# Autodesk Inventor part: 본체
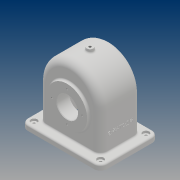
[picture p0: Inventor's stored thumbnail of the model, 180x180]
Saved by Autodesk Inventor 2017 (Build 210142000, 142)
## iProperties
Part Number: 본체
Material: 일반
Document SubType Name: Modeling
Designer: 20
Density: 1 g/cm^3
Appearance: 기본값
Author: 20
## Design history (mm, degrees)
sketch "스케치1"
  geometry: L1 (58, 13)-(58, -65); L2 (58, -65)-(-58, -65); L3 (-58, -65)-(-58, 13); A1 r 58 centre (0, 13) between (58, 13) and (-58, 13); 1 further point
  constraints: 6 end point, 2 point on circle, 2 tangent, 2 vertical, 1 centre point, 1 horizontal
  dimensions: "d0" = 58 distance from line of point (0, 0) L3; "d1" = 116 distance of L1.end L2.end; "d2" = 78 distance from line of A1.centre L2; "d3" = 65 distance from line of L2 point (0, 0); "d4" = 58 radius of A1 (derived)
extrude "돌출1" new body sketch "스케치1" stored distance "d5" = 77; taper "d6" = 0 deg
sketch "스케치2"
  geometry: L1 (58, -65)-(58, 13) reference; L2 (-58, 13)-(-58, -65) reference; L3 (52, -65)-(52, 13); L4 (-52, 13)-(-52, -65); L5 (52, -65)-(-52, -65); L6 (-58, -65)-(58, -65) reference; A1 r 58 centre (0, 13) between (58, 13) and (-58, 13) reference; A2 r 52 centre (0, 13) between (52, 13) and (-52, 13); 1 further point
  constraints: 6 end point, 2 point on circle, 1 centre point, 1 collinear, 1 horizontal, 2 other
  dimensions: "d9" = 6 distance between parallel lines of L1 L3
extrude "돌출2" cut sketch "스케치2" stored distance "d10" = 67; taper "d11" = 0 deg
sketch "스케치3"
  geometry: L1 (-64.83, 0)-(80.389, 0); L2 (33.5, -65)-(-33.5, -65) reference; L3 (33.5, 38)-(48.5, 38); L4 (48.5, 38)-(48.5, 20); L5 (48.5, 20)-(33.5, 20); L6 (33.5, 20)-(33.5, 38); L7 (33.5, 13)-(33.5, 65) reference; L8 (-38.5, 71)-(-38.5, 13) reference; L9 (-33.5, 65)-(-33.5, 13) reference; L10 (-33.5, 39.747)-(-19.5, 28); L11 (-19.5, 28)-(-19.5, 20); L12 (-19.5, 20)-(-43.5, 20); L13 (-43.5, 20)-(-43.5, 38); L14 (-43.5, 38)-(-38.5, 38); L15 (-38.5, 38)-(-38.5, 39.747); L16 (-38.5, 39.747)-(-33.5, 39.747); 1 further point
  constraints: 24 end point, 5 horizontal, 2 collinear, 2 parallel, 2 vertical, 1 perpendicular, 1 point on line
  dimensions: "d12" = 65 distance between parallel lines of L1 L2; "d14" = 40 diameter of L5 L1; "d15" = 76 diameter of L3 L1; "d16" = 87 distance between parallel lines of L4 L8; "d22" = 5 distance between parallel lines of L9 L8 (derived); "d23" = 15 distance of L4.end L5.end (derived); "d24" = 40 diameter of L12 L1; "d25" = 56 diameter of L10.end L1; "d26" = 76 diameter of L14 L1; "d27" = 24 distance of L11.end L12.end; "d29" = 5 distance between parallel lines of L8 L13; "d30" = 50 deg angle of L11 L10
revolve "회전1" sketch "스케치3" stored, may be unused: angle "d31" = 90 deg
sketch "스케치4"
  geometry: C1 r 20 at (0, 0) reference; C2 r 20 at (0, 0); 1 further point
  constraints: 1 centre point, 1 coincident
  dimensions: "d32" = 40 diameter of C2
extrude "돌출3" cut sketch "스케치4" stored distance "d33" = 67; taper "d34" = 0 deg
sketch "스케치5"
  geometry: L1 (-17, 16.5)-(133, 16.5); L2 (133, 16.5)-(133, -93.5); L3 (133, -93.5)-(-17, -93.5); L4 (-17, -93.5)-(-17, 16.5); L5 (-17, 16.5)-(133, -93.5); L6 (133, 16.5)-(-17, -93.5); L7 (6, -72)-(110, -72) reference; L8 (110, -5)-(6, -5); L9 (6, -5)-(6, -72); L10 (6, -72)-(110, -72); L11 (110, -72)-(110, -5); L12 (110, -5)-(6, -72); L13 (6, -5)-(110, -72); 2 further points
  constraints: 24 end point, 6 midpoint, 4 parallel, 2 horizontal, 2 perpendicular
  dimensions: "d35" = 150 distance of L2.end L3.end; "d36" = 110 distance of L1.end L2.end
extrude "돌출4" join sketch "스케치5" distance "d37" = 10; taper "d38" = 0 deg
node "작업 평면1"
sketch "스케치6"
  geometry: C1 r 6 at (75, -55); 1 further point
  constraints: 1 centre point, 1 coincident
  dimensions: "d40" = 12 diameter of C1
extrude "돌출5" join sketch "스케치6" stored distance "d41" = 10; taper "d42" = 0 deg
hole "구멍1" diameter "d45" = 4.459; stored, may be unused: countersink angle "d49" = 90 deg, drill point angle "d51" = 118 deg; dims "d43" = 10, "d44" = 10, "d46" = 10, "d47" = 4, "d48" = 2, "d50" = 50
fillet "모깎기1" dims "d52" = 12
sketch "스케치8"
  geometry: A1 r 12 centre (-121, 4.5) between (-121, 16.5) and (-133, 4.5) reference; 2 further points
  constraints: 1 coincident
hole "구멍2" sketch "스케치8" at (-121, 4.5) diameter "d53" = 5; stored, may be unused: countersink angle "d57" = 90 deg, drill point angle "d59" = 118 deg; dims "d54" = 10, "d55" = 12, "d56" = 4, "d58" = 50
fillet "모깎기2" dims "d66" = 13
fillet "모깎기3" dims "d67" = 8
fillet "모깎기5" dims "d69" = 3
chamfer "모따기1" distance "d70" = 1; stored, may be unused: second distance "d71" = 2, angle "d72" = 45 deg
sketch "스케치9"
  geometry: 2 further points
  constraints: 1 vertical alignment
  dimensions: "d73" = 29 distance of point (0, 0) point (0, 29)
hole "구멍3" sketch "스케치9" at (0, 29) diameter "d74" = 3.242; stored, may be unused: countersink angle "d78" = 90 deg, drill point angle "d80" = 118 deg; dims "d75" = 8, "d76" = 12, "d77" = 4, "d79" = 10
sketch "스케치10"
  geometry: C1 r 1.621 at (0, -29) reference; 2 further points
  constraints: 1 coincident
hole "구멍4" sketch "스케치10" at (0, -29) diameter "d84" = 3.242; stored, may be unused: countersink angle "d88" = 90 deg, drill point angle "d90" = 118 deg; dims "d85" = 8, "d86" = 12, "d87" = 4, "d89" = 10
fillet "모깎기6" dims "d94" = 3
sketch "스케치11"
  geometry: L1 (78, -17.5)-(78, 68.5) reference; L2 (0, -13)-(65, -13) reference; 2 further points
  constraints: 1 other
  dimensions: "d95" = 40 distance from line of L1 point (38, 25.5); "d96" = 38.5 distance from line of point (38, 25.5) L2
feature "엠보싱1" sketch "스케치11" dims "d0" = 58, "d1" = 116, "d2" = 78, "d3" = 65, "d4" = 58 (derived), "d97" = 0.5, "d98" = 0
feature "면 기울기1" dims angle "d99" = 5 deg
fillet "모깎기7" dims "d100" = 3
fillet "모깎기8" dims "d101" = 3
node "솔리드1"
pattern_linear "직사각형 패턴1" dims "d62" = 126, "d65" = 86
pattern_circular "원형 패턴1" dims angle "d82" = 360 deg
pattern_circular "원형 패턴2" dims angle "d92" = 360 deg
other parameters: "d39" = -142
